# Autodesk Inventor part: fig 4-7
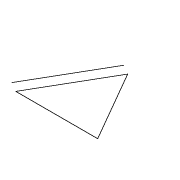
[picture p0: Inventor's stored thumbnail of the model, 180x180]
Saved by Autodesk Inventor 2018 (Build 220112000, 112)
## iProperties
Created: 2005-02
Part Number: fig 4-7
Document SubType Name: Modeling
Designer: CADCIM
Manufacturer: Standard
Standards Organization: Custom
Density: 1 g/cm^3
Material: Generic
Appearance: Default
Author: CADCIM
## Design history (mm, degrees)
sketch "Sketch1"
  geometry: L1 (-3.883, 28.419)-(-24.946, -8.063); L2 (-24.946, -8.063)-(17.18, -8.063); L3 (17.18, -8.063)-(-3.883, 28.419); L4 (-8.847, 31.285)-(-29.909, -5.197)
  constraints: 8 end point, 2 equal length, 1 horizontal, 1 parallel, 1 other
